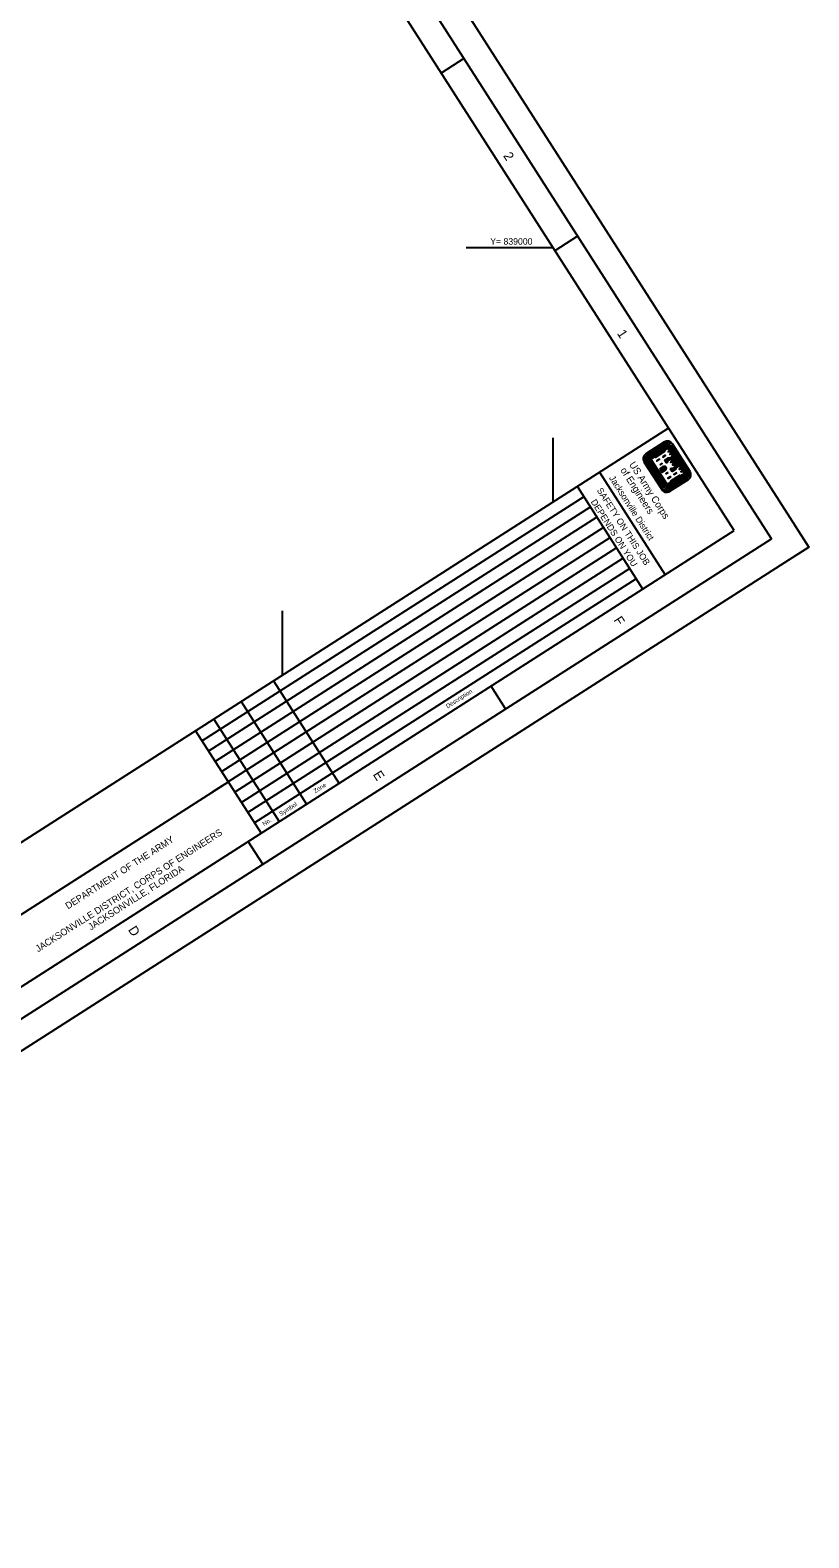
# Model space of a CAD drawing. Extents: x 582737 to 587973, y 836613 to 842151.
# Drawn here: x 586533 to 587973, y 836613 to 839402 of the extents above; entities that cross this region are included whole.
import ezdxf

# ---------------------------------------------------------------- set-up
doc = ezdxf.new("R2010")
doc.units = 0
for name, color, linetype in [('G-ANNO-NPLT', 7, 'Continuous'), ('G-ANNO-TEXT-LOGO', 7, 'Continuous'), ('G-ANNO-TEXT-TTLB', 7, 'Continuous'), ('G-ANNO-TTLB', 7, 'Continuous'), ('V-TOPO-COOR-STAT', 7, 'Continuous')]:
    doc.layers.add(name, color=color, linetype=linetype)

msp = doc.modelspace()

# ---------------------------------------------------------------- linework, layer by layer
at = {"layer": 'G-ANNO-NPLT'}
msp.add_lwpolyline([(585600.9, 842151.5), (587972.9, 838445.7), (585109.4, 836612.7), (582737.3, 840318.5)], close=True, dxfattribs=at)
msp.add_lwpolyline([(587930.8, 838418.7), (587972.9, 838445.7), (587946, 838487.8)], dxfattribs=at)
at = {"layer": 'G-ANNO-TEXT-LOGO'}
for p, q in [((587705.9, 838640), (587671.4, 838617.9)), ((587673.1, 838615.2), (587707.7, 838637.3)), ((587709.6, 838634.4), (587675, 838612.3)), ((587710, 838633.6), (587675.5, 838611.5)), ((587710.5, 838632.9), (587675.9, 838610.8)), ((587711, 838632.2), (587676.4, 838610.1)), ((587711.4, 838631.4), (587676.9, 838609.3)), ((587711.9, 838630.7), (587677.7, 838608.7)), ((587712.4, 838630), (587678.8, 838608.5)), ((587705.4, 838624.7), (587687.7, 838613.4)), ((587705.1, 838623.5), (587689.1, 838613.2)), ((587745, 838580.1), (587712.2, 838631.3)), ((587745.8, 838580.6), (587713, 838631.8)), ((587746.4, 838581), (587713.7, 838632.2)), ((587747.2, 838581.5), (587714.4, 838632.7)), ((587747.9, 838582), (587715.2, 838633.2)), ((587718, 838635), (587750.8, 838583.8)), ((587753.5, 838585.6), (587720.7, 838636.8)), ((587668.1, 838603.1), (587700.9, 838551.9)), ((587703.6, 838553.7), (587670.9, 838604.9)), ((587706.6, 838555.5), (587673.8, 838606.7)), ((587707.3, 838556), (587674.5, 838607.2)), ((587708, 838556.5), (587675.2, 838607.7)), ((587708.8, 838556.9), (587676, 838608.1)), ((587709.5, 838557.4), (587676.7, 838608.6)), ((587710, 838558.2), (587677.7, 838608.7)), ((587710.3, 838559.4), (587678.8, 838608.5)), ((587697.4, 838590.5), (587703, 838594.1)), ((587697.4, 838590.5), (587701.7, 838583.8)), ((587697.8, 838589.8), (587703.5, 838593.4)), ((587698.3, 838589.1), (587704, 838592.7)), ((587698.8, 838588.3), (587704.4, 838591.9)), ((587699.2, 838587.6), (587704.9, 838591.2)), ((587699.9, 838586.6), (587705.5, 838590.2)), ((587718.5, 838610.3), (587728.6, 838594.7)), ((587719.3, 838610.8), (587729.3, 838595.1)), ((587720, 838611.2), (587730, 838595.6)), ((587720.7, 838611.7), (587730.8, 838596.1)), ((587721.5, 838612.2), (587731.5, 838596.5)), ((587722.2, 838612.6), (587732.2, 838597)), ((587722.9, 838613.1), (587733, 838597.5)), ((587700.3, 838585.9), (587706, 838589.6)), ((587700.8, 838585.2), (587706.4, 838588.8)), ((587701.3, 838584.4), (587706.9, 838588)), ((587701.7, 838583.8), (587707.4, 838587.4)), ((587744.3, 838580.1), (587710, 838558.2)), ((587744.8, 838579.4), (587710.2, 838557.3)), ((587743.8, 838580.8), (587710.3, 838559.4)), ((587745.2, 838578.6), (587710.7, 838556.5)), ((587745.7, 838577.9), (587711.1, 838555.8)), ((587746.2, 838577.2), (587711.6, 838555.1)), ((587746.7, 838576.4), (587712.1, 838554.3)), ((587748.5, 838573.6), (587714, 838551.5)), ((587715.7, 838548.7), (587750.3, 838570.8)), ((587736.1, 838576.7), (587718.5, 838565.4)), ((587734.9, 838577), (587718.8, 838566.7))]:
    msp.add_line(p, q, dxfattribs=at)
for points in [[(587712.7, 838629.4), (587706.1, 838625.1), (587705.6, 838622.8), (587689.5, 838612.5), (587687.1, 838613), (587679.7, 838608.3), (587710.5, 838560.3), (587717.8, 838565), (587718.3, 838567.4), (587734.4, 838577.7), (587736.8, 838577.1), (587743.5, 838581.4), (587739.4, 838587.7), (587736.3, 838592.6), (587733.4, 838597.1), (587726.7, 838592.9), (587726.3, 838590.4), (587720.4, 838586.6), (587718.2, 838590.1), (587718.8, 838590.5), (587721.2, 838590), (587727.8, 838594.2), (587723.8, 838600.5), (587720.6, 838605.4), (587717.8, 838609.8), (587711.2, 838605.6), (587710.7, 838603.1), (587710.1, 838602.8), (587707.8, 838606.3), (587713.7, 838610.1), (587716.1, 838609.5), (587722.8, 838613.7), (587718.7, 838620.1), (587715.6, 838624.9), (587712.7, 838629.4)], [(587712.4, 838628.2), (587706.9, 838624.7), (587706.3, 838622.2), (587689.6, 838611.5), (587687.1, 838612.1), (587680.9, 838608.1), (587710.8, 838561.4), (587717, 838565.4), (587717.5, 838568), (587734.2, 838578.7), (587736.7, 838578), (587742.3, 838581.6), (587739.4, 838586.1), (587736.8, 838584.5), (587736.5, 838584.9), (587739.1, 838586.6), (587736.2, 838591), (587733.6, 838589.3), (587733.4, 838589.7), (587736, 838591.4), (587733.1, 838595.9), (587727.6, 838592.3), (587727, 838589.9), (587720.2, 838585.5), (587717.1, 838590.4), (587718.7, 838591.4), (587721.1, 838590.9), (587726.7, 838594.4), (587723.8, 838599), (587721.2, 838597.3), (587721, 838597.6), (587723.6, 838599.3), (587720.7, 838603.8), (587718.1, 838602.2), (587717.8, 838602.6), (587720.4, 838604.3), (587717.5, 838608.7), (587712, 838605.2), (587711.4, 838602.7), (587709.8, 838601.7), (587706.7, 838606.5), (587713.5, 838610.9), (587716, 838610.4), (587721.6, 838613.9), (587718.7, 838618.4), (587716.1, 838616.7), (587715.8, 838617.1), (587718.5, 838618.8), (587715.5, 838623.4), (587712.9, 838621.7), (587712.7, 838622), (587715.3, 838623.7), (587712.4, 838628.2)], [(587696.6, 838608.4), (587691.7, 838605.2), (587692, 838604.7), (587696.9, 838607.9), (587696.6, 838608.4)], [(587701.6, 838600.7), (587698.1, 838598.4), (587698.4, 838598), (587701.9, 838600.2), (587701.6, 838600.7)], [(587707.8, 838615.6), (587702.9, 838612.4), (587703.3, 838611.9), (587708.1, 838615.1), (587707.8, 838615.6)], [(587714.6, 838609), (587713.9, 838609.1), (587709.1, 838606), (587710.1, 838604.4), (587710.5, 838606.2), (587714.7, 838608.9)], [(587725.7, 838591.6), (587725.5, 838590.9), (587720.7, 838587.8), (587719.7, 838589.4), (587721.5, 838589), (587725.7, 838591.7)], [(587712.7, 838583.3), (587709.2, 838581.1), (587709, 838581.5), (587712.4, 838583.7), (587712.7, 838583.3)], [(587717.6, 838575.6), (587712.6, 838572.5), (587712.4, 838572.9), (587717.3, 838576.1), (587717.6, 838575.6)], [(587728.8, 838582.8), (587723.9, 838579.7), (587723.6, 838580.1), (587728.5, 838583.2), (587728.8, 838582.8)]]:
    msp.add_lwpolyline(points, dxfattribs=at)
for centre, major_axis, start_param, end_param in [((587711.7, 838631), (5.78, -9.02), 1.57078, 3.141576), ((587711.7, 838631), (4.04, -6.31), 1.57078, 3.141576), ((587711.7, 838631), (2.17, -3.38), 1.57078, 3.141576), ((587711.7, 838631), (1.7, -2.65), 1.57078, 3.141576), ((587711.7, 838631), (1.23, -1.92), 1.57078, 3.141576), ((587711.7, 838631), (0.76, -1.19), 1.57078, 3.141576), ((587711.7, 838631), (0.294, -0.46), 1.57078, 3.141576), ((587677.2, 838608.9), (-5.78, 9.02), 6.28317, 7.853966), ((587677.2, 838608.9), (-4.04, 6.31), 6.28317, 7.853966), ((587677.2, 838608.9), (-2.17, 3.38), 6.28317, 7.853966), ((587677.2, 838608.9), (-1.7, 2.65), 6.28317, 7.853966), ((587677.2, 838608.9), (-1.23, 1.92), 6.28317, 7.853966), ((587677.2, 838608.9), (-0.76, 1.19), 6.28317, 7.853966), ((587677.2, 838608.9), (-0.294, 0.46), 6.28317, 7.853966), ((587705.6, 838589.3), (-2.99, 4.68), 4.985832, 6.214359), ((587705.6, 838589.3), (-2.53, 3.95), 4.947465, 6.21436), ((587705.6, 838589.3), (-2.06, 3.22), 4.947465, 6.21436), ((587705.6, 838589.3), (-1.59, 2.48), 4.947465, 6.21436), ((587705.6, 838589.3), (-1.12, 1.75), 4.947465, 6.214359), ((587704, 838591.8), (1.12, -1.75), 0.068794, 1.335689), ((587704, 838591.8), (1.59, -2.48), 0.068794, 1.335689), ((587704, 838591.8), (2.06, -3.22), 0.068795, 1.335689), ((587704, 838591.8), (2.53, -3.95), 0.068795, 1.335689), ((587704, 838591.8), (2.99, -4.68), 0.068795, 1.29842), ((587744.5, 838579.9), (0.294, -0.46), 6.283169, 7.853965), ((587744.5, 838579.9), (0.76, -1.19), 6.283169, 7.853965), ((587744.5, 838579.9), (1.23, -1.92), 6.283169, 7.853965), ((587744.5, 838579.9), (1.7, -2.65), 6.283169, 7.853965), ((587744.5, 838579.9), (2.17, -3.38), 6.283169, 7.853965), ((587744.5, 838579.9), (4.04, -6.31), 6.28317, 7.853966), ((587744.5, 838579.9), (5.78, -9.02), 6.283169, 7.853965), ((587709.9, 838557.7), (5.78, -9.02), 4.712373, 6.28317), ((587709.9, 838557.7), (-4.04, 6.31), 1.570781, 3.141577), ((587709.9, 838557.7), (2.17, -3.38), 4.712373, 6.28317), ((587709.9, 838557.7), (1.7, -2.65), 4.712373, 6.28317), ((587709.9, 838557.7), (1.23, -1.92), 4.712373, 6.28317), ((587709.9, 838557.7), (0.76, -1.19), 4.712373, 6.28317), ((587709.9, 838557.7), (0.294, -0.46), 4.712373, 6.28317)]:
    msp.add_ellipse(centre, major_axis=major_axis, ratio=0.99964, start_param=start_param, end_param=end_param, dxfattribs=at)
at = {"layer": 'G-ANNO-TTLB'}
for p, q in [((587335.1, 839349.4), (587293, 839322.4)), ((587545.4, 839020.9), (587503.3, 838993.9)), ((587713.5, 838665.5), (585018.4, 836940.3)), ((587586.1, 838583.9), (587707.4, 838394.4)), ((587556.8, 838538.7), (586851.1, 838086.9)), ((587544.4, 838558), (587665.7, 838368.5)), ((587568.9, 838519.7), (586863.2, 838068)), ((587581.1, 838500.8), (586875.3, 838049)), ((587593.2, 838481.8), (586887.5, 838030.1)), ((587605.3, 838462.9), (586899.6, 838011.1)), ((587617.4, 838443.9), (586911.7, 837992.2)), ((587629.6, 838425), (586923.9, 837973.2)), ((587641.7, 838406), (586936, 837954.3)), ((587653.8, 838387.1), (586948.1, 837935.3)), ((586983.1, 838197.9), (587104.4, 838008.4)), ((587412.4, 838146.2), (587385.5, 838188.3)), ((586923.1, 838159.6), (587044.4, 837970.1)), ((586872.6, 838127.2), (586993.9, 837937.7)), ((586839, 838105.7), (586960.3, 837916.2)), ((586175.4, 837548.1), (586899.7, 838011)), ((586899.7, 838011), (586869.9, 837991.9)), ((586963.3, 837858.7), (586936.3, 837900.8))]:
    msp.add_line(p, q, dxfattribs=at)
for points in [[(582806.4, 840303.3), (585124.5, 836681.7), (587903.9, 838460.8), (585585.7, 842082.4)], [(587834.8, 838476), (585611, 841950.2), (582915.9, 840225), (585139.7, 836750.8)]]:
    msp.add_lwpolyline(points, close=True, dxfattribs=at)
at = {"layer": 'V-TOPO-COOR-STAT'}
for p, q in [((587339.1, 839000), (587499.4, 839000)), ((587500, 838528.8), (587500, 838647.6)), ((587000, 838208.8), (587000, 838327.5))]:
    msp.add_line(p, q, dxfattribs=at)

# ---------------------------------------------------------------- texts
at = {"layer": 'G-ANNO-TEXT-TTLB'}
for s, height, rotation, p in [('of Engineers', 13.086, 302.6232, (587623.8, 838587.9)), ('US Army Corps', 13.086, 302.6232, (587640.1, 838598.4)), ('Jacksonville District', 11.9, 302.6232, (587603, 838573.4)), ('DEPENDS ON YOU', 11.9, 302.6232, (587569.2, 838529.3)), ('SAFETY ON THIS JOB', 11.9, 302.6232, (587580.4, 838550.5)), ('Description', 8, 32.6232, (587305.1, 838146.9)), ('Zone', 8, 32.6232, (587060.4, 837989.9)), ('Symbol', 8, 32.6232, (586996.8, 837947.8)), ('JACKSONVILLE DISTRICT, CORPS OF ENGINEERS', 12.5, 32.6232, (586548, 837695.7)), ('No.', 8, 32.6232, (586965.8, 837929.1)), ('DEPARTMENT OF THE ARMY', 12.5, 32.6232, (586603.3, 837775.1)), ('JACKSONVILLE, FLORIDA', 12.5, 32.6232, (586645.4, 837736.2))]:
    msp.add_text(s, height=height, rotation=rotation, dxfattribs=at).set_placement(p)
at = {"layer": 'G-ANNO-TTLB'}
for s, p in [('2', (587407.3, 839169.5)), ('1', (587617.6, 838841)), ('F', (587611.4, 838310.6)), ('E', (587166.4, 838024.9)), ('D', (586713.7, 837737.7))]:
    msp.add_text(s, height=17.5, rotation=302.6232, dxfattribs=at).set_placement(p)
at = {"layer": 'V-TOPO-COOR-STAT'}
msp.add_text('Y= 839000', height=12, dxfattribs=at).set_placement((587383.9, 839005))

doc.saveas('drawing.dxf')
